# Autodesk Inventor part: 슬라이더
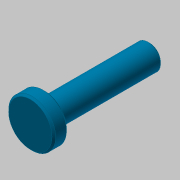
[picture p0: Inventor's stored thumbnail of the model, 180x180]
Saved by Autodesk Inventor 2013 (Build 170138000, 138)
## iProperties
Created: 2020-07
Part Number: 슬라이더
Material: 강철, 연강
Document SubType Name: Modeling
Designer: mduedu
Density: 1 g/cm^3
Author: mduedu
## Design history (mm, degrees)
sketch "스케치1"
  geometry: L1 (0, 0)-(8, 0); L2 (8, 0)-(8, 13); L3 (8, 13)-(0, 13); L4 (0, 13)-(0, 0); L5 (8, 0)-(66, 0); L6 (66, 0)-(66, 7); L7 (66, 7)-(8, 7); L8 (8, 7)-(8, 0)
  constraints: 16 end point, 4 parallel, 2 horizontal, 2 perpendicular
  dimensions: "d0" = 66 distance between parallel lines of L6 L4; "d2" = 26 diameter of L3 L1; "d3" = 14 diameter of L7 L5; "d4" = 8 distance of L2.end L3.end
revolve "회전1" sketch "스케치1" stored, may be unused: angle "d5" = 90 deg
chamfer "모따기1" distance "d6" = 1; stored, may be unused: second distance "d7" = 2, angle "d8" = 45 deg
hole "구멍1" diameter "d11" = 4.134; stored, may be unused: countersink angle "d15" = 90 deg, drill point angle "d17" = 118 deg; dims "d9" = 10, "d10" = 10, "d12" = 12, "d13" = 4, "d14" = 2, "d16" = 15
chamfer "모따기2" distance "d18" = 1; stored, may be unused: second distance "d19" = 2, angle "d20" = 45 deg
sketch "스케치2"
  geometry: L1 (51, 2.067)-(66, 2.067) reference; L2 (66, 2.067)-(66, -2.067) reference; L3 (0, 0)-(66, 0); L4 (66, 0)-(64, 0); L5 (64, 0)-(64, 2.067); L6 (66, 3.222)-(66, 0); L7 (66, 3.222)-(64, 2.067)
  constraints: 10 end point, 1 horizontal, 1 midpoint, 1 parallel, 1 perpendicular, 1 point on line
  dimensions: "d21" = 2 horizontal distance of L6.start L5.end; "d23" = 30 deg angle of L7 L3
revolve "회전2" sketch "스케치2" stored, may be unused: angle "d25" = 90 deg
node "솔리드1"
